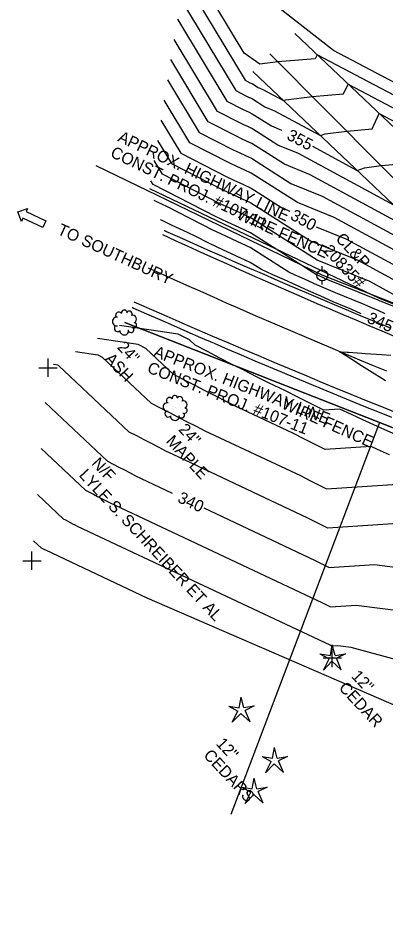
# Model space of a CAD drawing. Extents: x 487096 to 489566, y 221939 to 224454.
# Drawn here: x 487720.8 to 487821.4, y 223656.1 to 223900.8 of the extents above; entities that cross this region are included whole.
import ezdxf

# ---------------------------------------------------------------- set-up
doc = ezdxf.new("R2010")
doc.units = 0
for name, color, linetype in [('SV_BKLN_EARTH_TOP', 7, 'Continuous'), ('SV_FENC_FENCES', 7, 'Continuous'), ('SV_FENC_FENCES_TX', 7, 'Continuous'), ('SV_ROAD_BITRD', 7, 'Continuous'), ('SV_ROAD_GRAVRD', 7, 'Continuous'), ('SV_ROAD_ROAD_SY', 7, 'Continuous'), ('SV_ROAD_ROAD_TX', 7, 'Continuous'), ('SV_ROWL_HWYLOC', 7, 'Continuous'), ('SV_ROWL_PROP', 7, 'Continuous'), ('SV_ROWL_ROWL_TX', 7, 'Continuous'), ('SV_SURF_INDEX_CONTOUR', 7, 'Continuous'), ('SV_SURF_INTER_CONTOUR', 7, 'Continuous'), ('SV_SURF_SPOT', 7, 'Continuous'), ('SV_TRAF_PVMTL', 7, 'Continuous'), ('SV_TREE_TREEVEG', 7, 'Continuous'), ('SV_TREE_TREEVEG_TX', 7, 'Continuous'), ('SV_UTOH_OVERHEAD_LINES', 7, 'Continuous'), ('SV_UTOH_UPO', 7, 'Continuous'), ('SV_UTOH_UTOH_TX', 7, 'Continuous')]:
    doc.layers.add(name, color=color, linetype=linetype)

msp = doc.modelspace()

# ---------------------------------------------------------------- linework, layer by layer
at = {"layer": 'SV_BKLN_EARTH_TOP'}
msp.add_lwpolyline([(487899.13, 223790.17), (487849.86, 223824.73), (487785.15, 223886.13)], dxfattribs=at)
at = {"layer": 'SV_FENC_FENCES'}
for points in [[(487756.92, 223854.03), (487819.74, 223823.93), (487862.12, 223807.03)], [(488168.14, 223658.69), (488156.25, 223662.12), (488127.21, 223671.39), (488093.65, 223683.37), (488020.23, 223704.76), (487973.09, 223726.63), (487930.05, 223747.42), (487880.61, 223763.01), (487833.81, 223784.33), (487750.08, 223817.31)]]:
    msp.add_lwpolyline(points, dxfattribs=at)
at = {"layer": 'SV_ROAD_BITRD'}
for points in [[(487823.08, 223815.66), (487819.2, 223817.27), (487815.32, 223818.88), (487811.44, 223820.51), (487807.57, 223822.14), (487803.7, 223823.78), (487799.83, 223825.42), (487795.97, 223827.07), (487792.11, 223828.73), (487788.25, 223830.4), (487784.39, 223832.07), (487780.54, 223833.76), (487776.69, 223835.44), (487772.85, 223837.14), (487769.01, 223838.84), (487765.17, 223840.56), (487761.33, 223842.27), (487760.89, 223842.47)], [(487823.19, 223791.26), (487819.44, 223792.77), (487815.69, 223794.29), (487811.94, 223795.82), (487808.19, 223797.35), (487804.45, 223798.89), (487800.72, 223800.44), (487796.98, 223802), (487793.25, 223803.56), (487789.52, 223805.13), (487785.79, 223806.71), (487782.07, 223808.3), (487778.35, 223809.89), (487774.64, 223811.49), (487770.92, 223813.1), (487767.21, 223814.72), (487763.51, 223816.34), (487759.8, 223817.97), (487756.1, 223819.61), (487752.41, 223821.25), (487752.16, 223821.36)]]:
    msp.add_lwpolyline(points, dxfattribs=at)
at = {"layer": 'SV_ROAD_GRAVRD'}
for points in [[(487935.77, 223771.81), (487858.55, 223837.83), (487796.63, 223896.51)], [(487909.17, 223782.99), (487851.39, 223829), (487789.82, 223890.99)]]:
    msp.add_lwpolyline(points, dxfattribs=at)
at = {"layer": 'SV_ROAD_ROAD_SY'}
for p, q in [((487720.83, 223847.61), (487723.49, 223848.58)), ((487723.49, 223848.58), (487723.07, 223847.68)), ((487721.8, 223844.95), (487720.83, 223847.61)), ((487723.07, 223847.68), (487728.51, 223845.14)), ((487722.22, 223845.86), (487721.8, 223844.95)), ((487727.66, 223843.33), (487722.22, 223845.86)), ((487722.22, 223845.86), (487722.22, 223845.86)), ((487728.51, 223845.14), (487727.66, 223843.33))]:
    msp.add_line(p, q, dxfattribs=at)
at = {"layer": 'SV_ROWL_HWYLOC'}
for points in [[(487756.92, 223854.03), (487819.74, 223823.93), (487982.51, 223759.36), (488009.69, 223754.74), (488041.14, 223750.63), (488071.96, 223735.45), (488100.92, 223722.74), (488124.66, 223715.6), (488155.68, 223709.25), (488178.9, 223706.07), (488296.16, 223658.56), (488379.4, 223617.17), (488410.15, 223595.68), (488443.8, 223549.21), (488472.24, 223469.86), (488477.06, 223418.16), (488475.62, 223352.08), (488474.08, 223317.48), (488463.17, 223231.25), (488461.58, 223189.46)], [(487750.08, 223817.31), (487833.81, 223784.33), (487880.61, 223763.01), (487930.05, 223747.42), (487951.57, 223737.03), (487996.66, 223715.69), (488020.23, 223704.76), (488056.94, 223694.06), (488093.65, 223683.37), (488127.21, 223671.39), (488156.25, 223662.12), (488168.14, 223658.69), (488264.6, 223621.9)]]:
    msp.add_lwpolyline(points, dxfattribs=at)
at = {"layer": 'SV_ROWL_PROP'}
msp.add_line((487819.82, 223789.83), (487779.11, 223682.36), dxfattribs=at)
at = {"layer": 'SV_SURF_INDEX_CONTOUR'}
for points in [[(487764.57, 223900.44), (487778.01, 223878.01), (487782.53, 223875.7), (487783.35, 223875.31), (487784.17, 223874.93), (487784.99, 223874.55), (487790.24, 223871.2), (487793.04, 223870.06)], [(487760.01, 223872.76), (487765.43, 223863.71), (487777.91, 223857.31), (487780.17, 223856.26), (487782.43, 223855.21), (487784.7, 223854.15), (487794.07, 223848.17)], [(487801.55, 223865.62), (487813.73, 223859.01), (487815.76, 223859.73), (487820.29, 223860.31), (487825.64, 223860.75), (487828.31, 223866.5), (487852.04, 223853.98), (487869.68, 223851.29), (487879.08, 223850.8)], [(487814.86, 223819.69), (487812.24, 223820.84), (487810.74, 223821.45), (487807.21, 223822.99), (487803.76, 223824.51), (487800.37, 223826.01), (487797.05, 223827.49), (487793.81, 223828.94), (487790.62, 223830.37), (487787.51, 223831.78), (487784.42, 223833.75), (487780.69, 223835.48), (487776.99, 223837.21), (487773.3, 223838.93), (487769.16, 223841.05), (487766.1, 223842.5), (487763.11, 223843.92), (487760.19, 223845.31), (487759.86, 223845.47)], [(487802.49, 223843.56), (487810.68, 223840.22), (487839.71, 223824.46), (487845.74, 223822.07), (487846.58, 223821.71), (487847.41, 223821.36), (487848.27, 223821.03), (487849.12, 223820.71), (487849.97, 223820.4), (487854.74, 223817.68), (487860.74, 223817.09), (487863.51, 223819.14), (487864.76, 223818.36), (487868.89, 223826.63), (487868.91, 223826.62)], [(487821.48, 223801.25), (487820.47, 223801.91), (487817.82, 223803.59), (487817.11, 223804.05), (487814.23, 223805.89), (487813.82, 223806.16), (487810.73, 223808.13), (487810.59, 223808.22), (487808.94, 223809.28), (487811.03, 223809.15), (487811.35, 223809.13), (487815.03, 223808.89), (487815.95, 223808.82), (487819.01, 223808.63), (487820.51, 223808.51), (487822.95, 223808.35)], [(487728.29, 223795.32), (487745.33, 223779.27), (487746.9, 223778.45), (487748.46, 223777.64), (487750.01, 223776.84), (487751.55, 223776.04), (487753.08, 223775.26), (487754.6, 223774.49), (487763.07, 223770.5)], [(487771.75, 223766.41), (487802.26, 223752.04), (487803.55, 223751.39), (487804.83, 223750.74), (487806.1, 223750.11), (487818.48, 223750.92), (487846.53, 223747.27), (487853.95, 223745.24)]]:
    msp.add_lwpolyline(points, dxfattribs=at)
at = {"layer": 'SV_SURF_INTER_CONTOUR'}
for points in [[(487947.85, 223849.1), (487908.48, 223863.23), (487891.57, 223864.75), (487887.71, 223866.17), (487882.21, 223866.46), (487844.7, 223872.16), (487807.27, 223891.91), (487769.81, 223921.23), (487768.69, 223922.01), (487768.47, 223922.17), (487768.22, 223922.59)], [(487978.37, 223836.41), (487918.82, 223857.78), (487893.24, 223860.08), (487887.4, 223862.23), (487879.08, 223862.67), (487846.53, 223867.61), (487802.76, 223890.71), (487802.25, 223889.59), (487792.04, 223888.75), (487787.06, 223888.11), (487782.82, 223891.17), (487767.31, 223917.05)], [(487766.39, 223911.52), (487783.04, 223883.73), (487784.38, 223883.05), (487784.62, 223882.94), (487784.86, 223882.82), (487785.1, 223882.71), (487786.65, 223881.72), (487787.88, 223881.22), (487793.59, 223878.12), (487794.19, 223878.34), (487801.45, 223879.27), (487810.04, 223879.98), (487811.28, 223882.64), (487848.37, 223863.07), (487875.94, 223858.87), (487887.09, 223858.29), (487894.9, 223855.42), (487923.34, 223852.86), (487924.69, 223852.33), (487977.96, 223831.88)], [(487765.48, 223905.98), (487780.53, 223880.87), (487783.45, 223879.37), (487783.98, 223879.12), (487784.51, 223878.88), (487785.05, 223878.63), (487788.44, 223876.46), (487791.14, 223875.36), (487803.66, 223868.56), (487804.97, 223869.03), (487810.87, 223869.79), (487817.84, 223870.37), (487819.79, 223874.57), (487850.2, 223858.52), (487872.81, 223855.08), (487886.78, 223854.35), (487896.57, 223850.75), (487920.73, 223848.58), (487925.08, 223846.87), (487972.43, 223828.69)], [(487978.17, 223816.6), (487965.1, 223818.39), (487961.38, 223822.32), (487925.87, 223835.95), (487915.52, 223840.02), (487899.91, 223841.42), (487886.16, 223846.48), (487866.54, 223847.5), (487853.87, 223849.43), (487836.82, 223858.42), (487833.44, 223851.14), (487829.71, 223850.83), (487826.55, 223850.42), (487823.81, 223849.45), (487797.65, 223863.65), (487792.03, 223865.94), (487784.93, 223870.47), (487783.82, 223870.99), (487782.71, 223871.5), (487781.61, 223872.02), (487775.5, 223875.15), (487763.66, 223894.91)], [(487976.99, 223811.93), (487960.54, 223814.18), (487955.86, 223819.13), (487926.26, 223830.49), (487912.91, 223835.74), (487901.57, 223836.76), (487885.85, 223842.54), (487863.41, 223843.71), (487855.7, 223844.89), (487845.34, 223850.35), (487841.23, 223841.53), (487839.12, 223841.35), (487837.34, 223841.12), (487833.88, 223839.89), (487800.91, 223857.79), (487793.82, 223860.68), (487784.87, 223866.39), (487783.47, 223867.04), (487782.07, 223867.69), (487780.68, 223868.34), (487772.98, 223872.29), (487762.74, 223889.37)], [(487761.83, 223883.84), (487770.46, 223869.43), (487779.76, 223864.67), (487781.44, 223863.88), (487783.12, 223863.1), (487784.82, 223862.31), (487795.61, 223855.42), (487804.16, 223851.94), (487843.95, 223830.33), (487848.13, 223831.82), (487848.54, 223831.87), (487849.03, 223831.91), (487853.85, 223842.28), (487857.54, 223840.34), (487860.28, 223839.92), (487885.54, 223838.6), (487903.24, 223832.09), (487910.31, 223831.46), (487926.65, 223825.04), (487950.33, 223815.94), (487955.98, 223809.98), (487975.82, 223807.26)], [(487846.89, 223824.65), (487807.42, 223846.08), (487797.4, 223850.16), (487784.76, 223858.23), (487782.78, 223859.15), (487780.8, 223860.07), (487778.84, 223860.99), (487767.95, 223866.57), (487760.92, 223878.3)], [(487759.09, 223867.23), (487762.92, 223860.85), (487776.99, 223853.64), (487779.53, 223852.45), (487782.08, 223851.26), (487784.65, 223850.07), (487800.99, 223839.64), (487813.93, 223834.37), (487832.53, 223824.27)], [(487825.35, 223824.08), (487817.19, 223828.51), (487802.78, 223834.38), (487784.59, 223845.99), (487781.73, 223847.32), (487778.89, 223848.64), (487776.07, 223849.96), (487760.4, 223857.99), (487758.18, 223861.69)], [(487837, 223816.43), (487820.78, 223822.86), (487820.41, 223823.02), (487820.04, 223823.17), (487819.69, 223823.33), (487819.34, 223823.48), (487819, 223823.63), (487804.81, 223829.39), (487804.48, 223829.54), (487804.15, 223829.68), (487803.84, 223829.82), (487803.52, 223829.96), (487803.22, 223830.1), (487802.92, 223830.23), (487802.62, 223830.36), (487784.53, 223841.91), (487781.39, 223843.37), (487778.26, 223844.83), (487775.14, 223846.28), (487757.89, 223855.13), (487757.27, 223856.16)], [(487821.45, 223819.7), (487819.46, 223820.56), (487817.52, 223821.4), (487815.62, 223822.23), (487807.78, 223825.42), (487805.85, 223826.26), (487803.95, 223827.1), (487802.1, 223827.92), (487800.29, 223828.72), (487798.51, 223829.52), (487796.77, 223830.3), (487795.06, 223831.07), (487784.47, 223837.83), (487781.04, 223839.42), (487777.62, 223841.02), (487774.22, 223842.61), (487761.58, 223849.08), (487760.42, 223849.64), (487759.28, 223850.18), (487758.17, 223850.71), (487758.04, 223850.77)], [(487824.25, 223786.54), (487821.32, 223787.87), (487818.32, 223789.23), (487815.27, 223790.63), (487812.15, 223792.06), (487808.97, 223793.53), (487804.64, 223793.25), (487801.17, 223794.98), (487797.66, 223796.74), (487794.13, 223798.52), (487789.46, 223800.72), (487786.17, 223802.39), (487782.86, 223804.09), (487779.53, 223805.8), (487776.17, 223807.54), (487772.79, 223809.29), (487769.38, 223811.07), (487767.87, 223812.5), (487764.73, 223814.07), (487748.67, 223816.47)], [(487822.63, 223780.97), (487820.99, 223781.72), (487819.31, 223782.49), (487817.59, 223783.29), (487805.01, 223782.46), (487802.08, 223783.92), (487799.13, 223785.4), (487796.16, 223786.9), (487780.75, 223794.16), (487777.9, 223795.61), (487775.03, 223797.07), (487772.15, 223798.56), (487769.24, 223800.06), (487766.32, 223801.58), (487763.37, 223803.12), (487755.91, 223810.15), (487753.74, 223811.24), (487742.63, 223812.9)], [(487736.6, 223809.32), (487742.76, 223808.4), (487743.96, 223807.8), (487757.36, 223795.17), (487759.84, 223793.87), (487762.31, 223792.59), (487764.77, 223791.32), (487767.21, 223790.06), (487769.63, 223788.83), (487772.03, 223787.6), (487798.2, 223775.28), (487800.61, 223774.06), (487803, 223772.86), (487805.37, 223771.68), (487826.22, 223773.04)], [(487974.88, 223715.46), (487963.2, 223719.55), (487951.33, 223726.23), (487942.64, 223727.98), (487917.87, 223727.61), (487881.75, 223742.48), (487866.49, 223756.07), (487863.73, 223756.82), (487823.49, 223762.06), (487805.74, 223760.9), (487803.91, 223761.8), (487802.08, 223762.72), (487800.23, 223763.66), (487763.32, 223781.04), (487761.36, 223782.04), (487759.38, 223783.05), (487757.39, 223784.08), (487755.39, 223785.11), (487753.37, 223786.16), (487751.34, 223787.22), (487732, 223805.45), (487731.77, 223805.56), (487730.56, 223805.74)], [(487727.24, 223782.7), (487739.31, 223771.32), (487740.43, 223770.74), (487741.53, 223770.16), (487742.63, 223769.59), (487743.72, 223769.03), (487744.81, 223768.48), (487745.89, 223767.93), (487804.29, 223740.42), (487805.02, 223740.05), (487805.75, 223739.69), (487806.46, 223739.33), (487813.47, 223739.79), (487829.34, 223737.72), (487873.62, 223725.63), (487883.15, 223717.14), (487905.72, 223707.85), (487946.16, 223708.46), (487951.99, 223707.95), (487955.64, 223708.72), (487977.16, 223701.17)], [(487978.3, 223694.02), (487963.1, 223699.35), (487949.56, 223696.51), (487927.94, 223698.4), (487899.64, 223697.97), (487883.85, 223704.47), (487877.18, 223710.41), (487812.14, 223728.17), (487808.45, 223728.65), (487806.83, 223728.54), (487806.66, 223728.63), (487806.49, 223728.71), (487806.32, 223728.8), (487737.17, 223761.37), (487736.54, 223761.69), (487735.9, 223762.02), (487735.25, 223762.35), (487734.61, 223762.69), (487733.95, 223763.03), (487733.3, 223763.37), (487726.18, 223770.08)], [(487970.56, 223689.99), (487947.14, 223685.07), (487909.72, 223688.34), (487893.57, 223688.09), (487884.55, 223691.8), (487880.75, 223695.19), (487833.97, 223707.96), (487756.27, 223741.71), (487728.46, 223754.81), (487728.26, 223754.91), (487728.07, 223755.01), (487727.88, 223755.11), (487727.68, 223755.21), (487727.48, 223755.32), (487727.28, 223755.42), (487725.13, 223757.45)]]:
    msp.add_lwpolyline(points, dxfattribs=at)
at = {"layer": 'SV_SURF_SPOT'}
for p, q in [((487729.09, 223802.37), (487729.09, 223807.37)), ((487726.59, 223804.87), (487731.59, 223804.87)), ((487729.09, 223804.87), (487729.09, 223804.87)), ((487724.67, 223749.46), (487724.67, 223754.46)), ((487722.16, 223751.96), (487727.17, 223751.96)), ((487724.67, 223751.96), (487724.67, 223751.96)), ((487806.94, 223722.78), (487806.94, 223727.78)), ((487804.44, 223725.28), (487809.44, 223725.28)), ((487806.94, 223725.28), (487806.94, 223725.28))]:
    msp.add_line(p, q, dxfattribs=at)
at = {"layer": 'SV_TRAF_PVMTL'}
for points in [[(487824.19, 223813.39), (487820.62, 223814.88), (487817.06, 223816.38), (487813.5, 223817.88), (487809.94, 223819.39), (487806.38, 223820.91), (487802.83, 223822.44), (487799.28, 223823.97), (487795.74, 223825.51), (487792.19, 223827.06), (487788.65, 223828.62), (487785.12, 223830.18), (487781.58, 223831.75), (487778.05, 223833.33), (487774.53, 223834.91), (487771.01, 223836.51), (487767.49, 223838.11), (487763.97, 223839.71), (487760.49, 223841.31)], [(487821.85, 223803.9), (487818.18, 223805.42), (487814.51, 223806.95), (487810.84, 223808.48), (487807.18, 223810.02), (487803.52, 223811.57), (487799.86, 223813.13), (487796.21, 223814.69), (487792.56, 223816.26), (487788.91, 223817.84), (487785.27, 223819.42), (487781.63, 223821.01), (487777.99, 223822.61), (487774.36, 223824.22), (487770.73, 223825.83), (487767.1, 223827.45), (487763.47, 223829.08), (487759.85, 223830.72), (487756.56, 223832.22)], [(487824.73, 223792.39), (487820.51, 223794.11), (487816.29, 223795.83), (487812.07, 223797.56), (487807.85, 223799.3), (487803.64, 223801.04), (487799.43, 223802.8), (487795.22, 223804.56), (487791.02, 223806.32), (487786.81, 223808.1), (487782.62, 223809.88), (487778.42, 223811.67), (487774.23, 223813.47), (487770.04, 223815.27), (487765.86, 223817.09), (487761.67, 223818.9), (487757.5, 223820.73), (487753.32, 223822.56), (487752.69, 223822.84)]]:
    msp.add_lwpolyline(points, dxfattribs=at)
at = {"layer": 'SV_TREE_TREEVEG'}
for p, q in [((487750.08, 223817.31), (487750.08, 223817.31)), ((487763.96, 223793.87), (487763.96, 223793.87)), ((487806.42, 223725.95), (487806.94, 223728.86)), ((487807.7, 223725.95), (487806.94, 223728.86)), ((487803.54, 223726.39), (487806.05, 223725.02)), ((487803.54, 223726.39), (487806.42, 223725.95)), ((487807.7, 223725.95), (487810.5, 223726.44)), ((487810.5, 223726.44), (487808.04, 223725.2)), ((487804.51, 223721.94), (487806.05, 223725.02)), ((487806.82, 223724.38), (487804.51, 223721.94)), ((487806.82, 223724.38), (487809.37, 223722.06)), ((487806.94, 223725.28), (487806.94, 223725.28)), ((487809.37, 223722.06), (487808.04, 223725.2)), ((487781.44, 223711.65), (487781.96, 223714.56)), ((487782.73, 223711.66), (487781.96, 223714.56)), ((487778.56, 223712.09), (487781.08, 223710.72)), ((487778.56, 223712.09), (487781.44, 223711.65)), ((487782.73, 223711.66), (487785.53, 223712.14)), ((487785.53, 223712.14), (487783.07, 223710.91)), ((487779.53, 223707.64), (487781.08, 223710.72)), ((487781.84, 223710.09), (487779.53, 223707.64)), ((487781.84, 223710.09), (487784.4, 223707.77)), ((487781.96, 223710.99), (487781.96, 223710.99)), ((487784.4, 223707.77), (487783.07, 223710.91)), ((487790.59, 223697.78), (487791.11, 223700.69)), ((487791.87, 223697.78), (487791.11, 223700.69)), ((487787.7, 223698.22), (487790.22, 223696.85)), ((487787.7, 223698.22), (487790.59, 223697.78)), ((487788.68, 223693.77), (487790.22, 223696.85)), ((487791.11, 223697.11), (487791.11, 223697.11)), ((487791.87, 223697.78), (487794.67, 223698.27)), ((487794.67, 223698.27), (487792.21, 223697.03)), ((487793.54, 223693.89), (487792.21, 223697.03)), ((487790.98, 223696.21), (487788.68, 223693.77)), ((487790.98, 223696.21), (487793.54, 223693.89)), ((487785.01, 223689.39), (487785.53, 223692.3)), ((487786.3, 223689.39), (487785.53, 223692.3)), ((487782.13, 223689.83), (487784.64, 223688.46)), ((487782.13, 223689.83), (487785.01, 223689.39)), ((487786.3, 223689.39), (487789.09, 223689.88)), ((487789.09, 223689.88), (487786.63, 223688.64)), ((487783.1, 223685.37), (487784.64, 223688.46)), ((487785.41, 223687.82), (487783.1, 223685.37)), ((487785.41, 223687.82), (487787.97, 223685.5)), ((487785.53, 223688.72), (487785.53, 223688.72)), ((487787.97, 223685.5), (487786.63, 223688.64))]:
    msp.add_line(p, q, dxfattribs=at)
for centre, radius, start, end in [((487748.47, 223819.27), 0.874, 35.9933, 211.459), ((487749.97, 223819.96), 0.75, 23.2911, 192.3579), ((487751.29, 223819.55), 0.85, 345.5308, 152.7093), ((487752.25, 223818.19), 1.06, 294.1859, 111.1082), ((487747.88, 223817.56), 1.17, 79.3292, 279.9889), ((487748.17, 223815.71), 0.922, 137.0157, 304.5501), ((487763.85, 223796.52), 0.75, 23.2911, 192.3579), ((487761.76, 223794.12), 1.17, 79.3292, 279.9889), ((487762.35, 223795.83), 0.874, 35.9933, 211.459), ((487765.16, 223796.11), 0.85, 345.5308, 152.7093), ((487766.12, 223794.75), 1.06, 294.1859, 111.1082), ((487762.04, 223792.27), 0.922, 137.0157, 304.5501)]:
    msp.add_arc(centre, radius, start, end, dxfattribs=at)
for centre, major_axis, ratio, start_param, end_param in [((487752.54, 223816.54), (0.822, -0.013), 0.901056, 4.216583, 7.444153), ((487749.96, 223814.97), (-1.2, 0.16), 0.902156, 0, 3.5401), ((487751.8, 223815.34), (0.08, -0.798), 0.999752, 5.391582, 8.241319), ((487765.68, 223791.9), (0.08, -0.798), 0.999752, 5.391582, 8.241319), ((487766.41, 223793.1), (0.822, -0.013), 0.901056, 4.216583, 7.444153), ((487763.83, 223791.53), (-1.2, 0.16), 0.902156, 0, 3.5401)]:
    msp.add_ellipse(centre, major_axis=major_axis, ratio=ratio, start_param=start_param, end_param=end_param, dxfattribs=at)
at = {"layer": 'SV_UTOH_OVERHEAD_LINES'}
msp.add_lwpolyline([(488477.01, 222631.44), (488424.13, 222778.25), (488391.68, 223012.96), (488449.87, 223205.72), (488470, 223438.33), (488349.56, 223622.89), (488159.18, 223693.12), (487993.17, 223755.78), (487804.2, 223830.22), (487742.26, 223860.21)], dxfattribs=at)
at = {"layer": 'SV_UTOH_UPO'}
for p, q in [((487804.17, 223831.69), (487804.17, 223832.69)), ((487804.19, 223827.72), (487804.19, 223828.72))]:
    msp.add_line(p, q, dxfattribs=at)
msp.add_circle((487804.17, 223830.21), 1.5, dxfattribs=at)

# ---------------------------------------------------------------- texts
at = {"layer": 'SV_FENC_FENCES_TX'}
for p in [(487780.53, 223845.77), (487792.78, 223793.84)]:
    msp.add_text('WIRE FENCE', height=3.2, rotation=335.9283, dxfattribs=at).set_placement(p)
at = {"layer": 'SV_ROAD_ROAD_TX'}
msp.add_text('TO SOUTHBURY', height=3.2, rotation=335.4794, dxfattribs=at).set_placement((487731.41, 223841.65))
at = {"layer": 'SV_ROWL_ROWL_TX'}
for s, rotation, p in [('APPROX. HIGHWAY LINE', 334.3985, (487747.94, 223867.1)), ('CONST. PROJ. #107-11', 334.3985, (487745.91, 223862.86)), ('APPROX. HIGHWAY LINE', 338.4972, (487757.73, 223808.04)), ('CONST. PROJ. #107-11', 338.4972, (487756.01, 223803.67)), ('N/F', 313, (487740.82, 223778.47)), ('LYLE S. SCHREIBER ET AL', 313, (487737.38, 223775.27))]:
    msp.add_text(s, height=3.2, rotation=rotation, dxfattribs=at).set_placement(p)
at = {"layer": 'SV_SURF_INDEX_CONTOUR'}
for s, rotation, p in [('355', 332.4603, (487794.21, 223867.65)), ('350', 331.2759, (487795.19, 223845.73)), ('345', 336.5471, (487816.2, 223817.37)), ('340', 334.7761, (487764.33, 223768.14))]:
    msp.add_text(s, height=3.2, rotation=rotation, dxfattribs=at).set_placement(p)
at = {"layer": 'SV_TREE_TREEVEG_TX'}
for s, p in [('24"', (487747.85, 223810.34)), ('ASH', (487744.41, 223807.13)), ('24"', (487764.63, 223787.79)), ('MAPLE', (487761.19, 223784.58)), ('12"', (487811.96, 223720.14)), ('CEDAR', (487808.52, 223716.93)), ('12"', (487774.91, 223701.63)), ('CEDARS', (487771.47, 223698.43))]:
    msp.add_text(s, height=3.2, rotation=313.0386, dxfattribs=at).set_placement(p)
at = {"layer": 'SV_UTOH_UTOH_TX'}
for s, p in [('CL&P', (487807.64, 223840.07)), ('20835#', (487804.21, 223836.86))]:
    msp.add_text(s, height=3.2, rotation=313.0386, dxfattribs=at).set_placement(p)

doc.saveas('drawing.dxf')
